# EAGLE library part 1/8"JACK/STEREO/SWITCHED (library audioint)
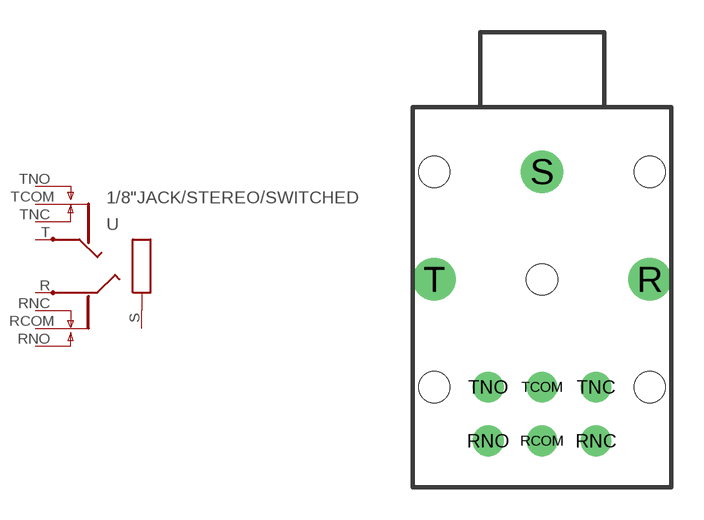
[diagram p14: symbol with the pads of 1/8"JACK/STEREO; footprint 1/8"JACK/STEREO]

Designator prefix -

## 1/8"JACK/STEREO/SWITCHED  [1/8"JACK/STEREO]
R  R  pas
RCOM  RCOM  pas
RNC  RNC  pas
RNO  RNO  pas
S  S  pas
T  T  pas
TCOM  TCOM  pas
TNC  TNC  pas
TNO  TNO  pas

## Footprint 1/8"JACK/STEREO (pad centres in mm)
drill 1.245 pad 1.981 round: R 5,-8; S 0,-3; T -5,-8
drill 0.813 pad 1.422 round: RCOM 0,-15.5; RNC 2.5,-15.5; RNO -2.5,-15.5; TCOM 0,-13; TNC 2.5,-13; TNO -2.5,-13
hole 1.448 at -5,-3
hole 1.448 at 5,-3
hole 1.448 at 0,-8
hole 1.448 at -5,-13
hole 1.448 at 5,-13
